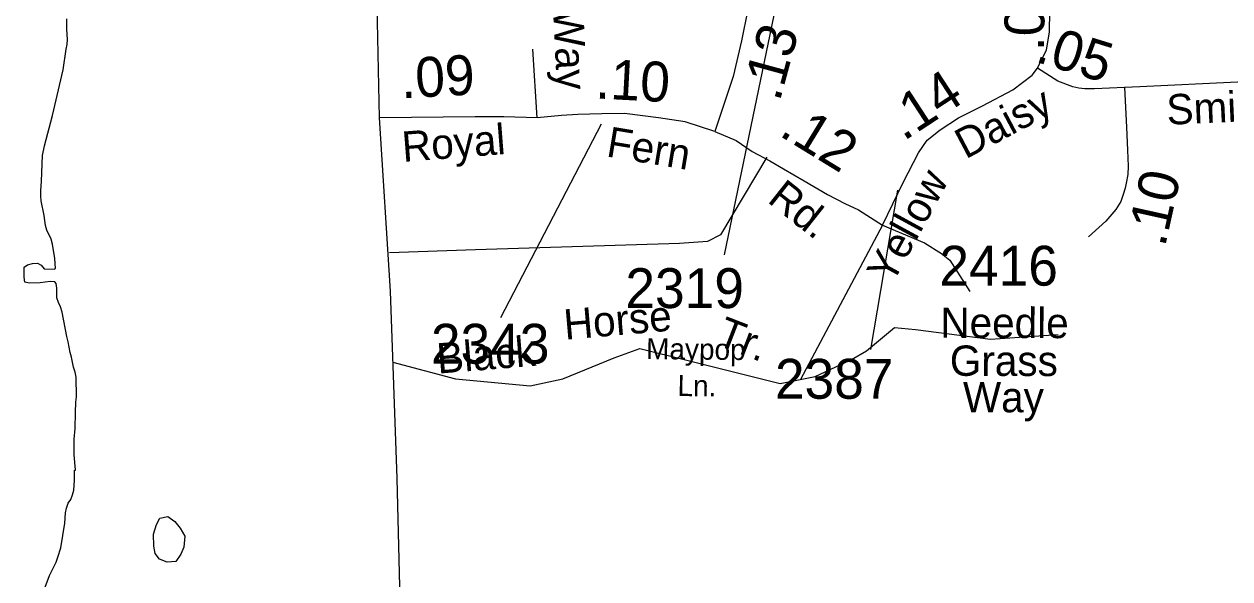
# Model space of a CAD drawing. Extents: x 2290055 to 2389491, y 66597 to 237875.
# Drawn here: x 2325602 to 2329384, y 120730 to 122469 of the extents above; entities that cross this region are included whole.
import ezdxf

# ---------------------------------------------------------------- set-up
doc = ezdxf.new("R2010")
doc.units = 0
for name, color, linetype in [('Exist Hydrographic Island Shore', 7, 'Continuous'), ('Exist Hydrographic Pond Under 1500 Sq Ft', 7, 'Continuous'), ('Exist Road Non-System Type 51', 7, 'Continuous'), ('Exist Road Non-System Type 51 Label', 7, 'Continuous'), ('Exist Road Secondary Mileage Hundredths English Label', 7, 'Continuous'), ('Exist Road Secondary Type 51 Attributed', 7, 'Continuous'), ('Exist Road Secondary Type 51 Label', 7, 'Continuous'), ('Exist Road Secondary Type 51 Number Label', 7, 'Continuous')]:
    doc.layers.add(name, color=color, linetype=linetype)

msp = doc.modelspace()

# ---------------------------------------------------------------- linework, layer by layer
at = {"layer": 'Exist Hydrographic Island Shore'}
msp.add_lwpolyline([(2325665.2, 120696.2), (2325681.5, 120740.3), (2325703.2, 120783), (2325708.5, 120798), (2325717, 120827.3), (2325730, 120904.5), (2325732.5, 120936.7), (2325735, 120952.2), (2325740, 120967.3), (2325749, 120979.4), (2325754.2, 120993.7), (2325758, 121008.6), (2325759.7, 121023.8), (2325760.5, 121040.1), (2325760.7, 121071), (2325763, 121070.6), (2325763.7, 121071.9), (2325759.7, 121119.2), (2325759.2, 121151), (2325759.5, 121167.7), (2325762.5, 121201.3), (2325763, 121251.3), (2325764.5, 121283.6), (2325766.5, 121300.9), (2325765.5, 121362.3), (2325762.7, 121377.8), (2325757.5, 121393.9), (2325751, 121425.5), (2325747, 121440.2), (2325740.2, 121473.6), (2325736.2, 121489.5), (2325722, 121566.5), (2325716.7, 121582.6), (2325710.5, 121596.2), (2325705.2, 121610.8), (2325704.5, 121641.3), (2325703.2, 121656.4), (2325698.7, 121661.7), (2325683.7, 121661.9), (2325668.5, 121660.7), (2325652.2, 121657.8), (2325619, 121656.8), (2325604, 121660.4), (2325602.2, 121675.6), (2325602.5, 121707.1), (2325613, 121715), (2325628.5, 121719), (2325644, 121720), (2325656, 121714), (2325665.5, 121701.7), (2325696.5, 121701.5), (2325700.2, 121703.5), (2325698.7, 121734.1), (2325691.7, 121779.9), (2325687.5, 121795.5), (2325673.5, 121822.9), (2325669, 121838), (2325665.2, 121869.5), (2325656, 121914.9), (2325654.5, 121930.1), (2325654.5, 121946.3), (2325657, 121977.1), (2325659.7, 122057.2), (2325666, 122087.7), (2325691.2, 122183), (2325724.7, 122326), (2325733.7, 122390.3), (2325737.7, 122405.5), (2325738.7, 122421.3), (2325736, 122453.8), (2325736, 122485.5)], dxfattribs=at)
at = {"layer": 'Exist Hydrographic Pond Under 1500 Sq Ft'}
msp.add_lwpolyline([(2326050.7, 120782.5), (2326027, 120792.4), (2326013, 120810.1), (2326009, 120832.9), (2326007.7, 120870.6), (2326017.5, 120900.4), (2326028, 120920.9), (2326053.2, 120925.4), (2326074.5, 120910.2), (2326092, 120889.6), (2326106, 120864.3), (2326103.5, 120829.9), (2326094.2, 120807.8), (2326078, 120785), (2326050.7, 120782.5)], dxfattribs=at)
at = {"layer": 'Exist Road Non-System Type 51'}
for points in [[(2327931.6, 122051.9), (2327786.7, 121808.3), (2327745.9, 121788.1), (2327657.5, 121781.4), (2327018.3, 121761.4), (2326748.4, 121752.4)], [(2328294.8, 121839.5), (2328037.4, 121355.5)], [(2328294.8, 121839.5), (2328426, 121783.1), (2328479.4, 121749.7), (2328506.1, 121729.7), (2328569.1, 121630.8)], [(2326759.2, 121409), (2326955.1, 121357.4), (2327189.6, 121335.4), (2327292.1, 121357.4), (2327453.3, 121423.4), (2327533.9, 121452.7), (2327680.5, 121416.1), (2327973.5, 121342.8), (2328083.5, 121364.8), (2328197, 121417.9), (2328244.6, 121445.4), (2328332.6, 121518.7), (2328398.5, 121511.4), (2328633, 121482.1), (2328845.4, 121496.7)]]:
    msp.add_lwpolyline(points, dxfattribs=at)
at = {"layer": 'Exist Road Secondary Type 51 Attributed'}
msp.add_line((2327211.3, 122175.8), (2327197.9, 122390.3), dxfattribs=at)
for points in [[(2326717.2, 122175.8), (2326707.1, 122627.5), (2326692.1, 123179.7)], [(2327862.1, 122788.2), (2327889.7, 122682.8), (2327884.7, 122612.5), (2327872.2, 122514.6), (2327852.1, 122416.7), (2327826.8, 122305), (2327769.3, 122132.2)], [(2328781.3, 122330.7), (2328809, 122389.1), (2328819, 122444.3), (2328819.6, 122510.2), (2328815.4, 122608.8), (2328809.3, 122710)], [(2330085.3, 122422.4), (2330035.4, 122426.9), (2330011, 122426.9), (2329988.9, 122426.5), (2329955.8, 122422.4), (2329927.2, 122417.8), (2329898.5, 122405.7), (2329827.7, 122373.7), (2329748.5, 122341.3), (2329674.2, 122319.2), (2329591.4, 122300.7), (2329536.6, 122291.9), (2329408.6, 122287), (2329102, 122272.9), (2329053.7, 122271)], [(2328294.8, 121839.5), (2328360, 121972.5), (2328407.7, 122065.4), (2328435.3, 122105.5), (2328475.4, 122138.1), (2328533.1, 122175.8), (2328608.3, 122213.4), (2328703.6, 122263.6), (2328763.8, 122308.8), (2328781.3, 122330.7)], [(2329053.7, 122271), (2328959.3, 122266.5), (2328929.6, 122266.1), (2328910.9, 122268), (2328891.5, 122272.9), (2328844.3, 122290.9), (2328781.3, 122330.7)], [(2329053.7, 122271), (2329060.5, 122145.7), (2329063.6, 122074.2), (2329065.1, 122023.7), (2329064.2, 121998.1), (2329059.3, 121970.3), (2329055.9, 121955.2), (2329049.8, 121934.8), (2329041.9, 121913.2), (2329027, 121888.2), (2328995.7, 121851.1), (2328940.6, 121802.1)], [(2327211.3, 122175.8), (2327107.2, 122178.3), (2327016.9, 122178.3), (2326717.2, 122175.8)], [(2326929.9, 116468.6), (2326914.2, 116526.2), (2326903.7, 116604.7), (2326893.2, 116772.3), (2326885.4, 117136.2), (2326877, 117384.2), (2326871.6, 117896.1), (2326831.4, 119069.9), (2326815.4, 119571.1), (2326794, 120155.3), (2326772.5, 121045), (2326751.1, 121631.9), (2326717.2, 122175.8)], [(2327769.3, 122132.2), (2327675.4, 122162.6), (2327592.5, 122175.8), (2327485.2, 122189.4), (2327414.4, 122188.3), (2327339.2, 122185.8), (2327287.8, 122183.3), (2327211.3, 122175.8)], [(2327769.3, 122132.2), (2327835.6, 122104.5), (2327886, 122070.4), (2327941.2, 122040.3), (2327983.8, 122015.2), (2328049, 121977.5), (2328121.7, 121934.9), (2328176.9, 121907.3), (2328219.6, 121887.2), (2328294.8, 121839.5)]]:
    msp.add_lwpolyline(points, dxfattribs=at)
at = {"layer": 'Exist Road Secondary Type 51 Number Label'}
for p, q in [((2328020.4, 122817.7), (2327798.1, 121745.6)), ((2327412.7, 122155.7), (2327096.5, 121548)), ((2328341.5, 121948.2), (2328257.5, 121449.2))]:
    msp.add_line(p, q, dxfattribs=at)

# ---------------------------------------------------------------- texts
at = {"layer": 'Exist Road Non-System Type 51 Label'}
for s, rotation, p in [('Horse', 4.9412, (2327299, 121479.7)), ('Tr.', 338.8588, (2327769.3, 121465.4)), ('Black', 4.6452, (2326900.3, 121373.4))]:
    msp.add_text(s, height=95, rotation=rotation, dxfattribs=at).set_placement(p)
at = {"layer": 'Exist Road Secondary Mileage Hundredths English Label'}
for s, rotation, p in [('.07', 89.4944, (2328801.5, 122384.2)), ('.13', 74.7563, (2327971.8, 122223.4)), ('.05', 342.8308, (2328770.2, 122352.6)), ('.09', 3.157, (2326786.3, 122236.5)), ('.10', 356.9854, (2327392.7, 122236.5)), ('.14', 33.1272, (2328361, 122100.9)), ('.12', 328.5436, (2327966.9, 122121.7)), ('.10', 77.5084, (2329180.5, 121767.7))]:
    msp.add_text(s, height=125, rotation=rotation, dxfattribs=at).set_placement(p)
at = {"layer": 'Exist Road Secondary Type 51 Label'}
for s, height, rotation, p in [('Willow Way', 95, 272.8985, (2327240.8, 122916.9)), ('Daisy', 95, 27.8067, (2328555.2, 122044.8)), ('Smilax', 95, 2.6221, (2329187.7, 122153.5)), ('Royal', 95, 4.4706, (2326791, 122037.1)), ('Fern', 95, 350.5304, (2327425.5, 122054.9)), ('Yellow', 95, 61.4208, (2328324.8, 121650.6)), ('Rd.', 95, 321.6107, (2327930.3, 121913.4)), ('Needle', 95, 359.8228, (2328476.1, 121485.9)), ('Maypop', 65.62, 359.4391, (2327553, 121419.1)), ('Grass', 95, 359.8228, (2328505.8, 121366.9)), ('Ln.', 65.62, 359.4391, (2327651.5, 121303.3)), ('Way', 95, 359.8228, (2328546.7, 121252.8))]:
    msp.add_text(s, height=height, rotation=rotation, dxfattribs=at).set_placement(p)
at = {"layer": 'Exist Road Secondary Type 51 Number Label'}
for s, p in [('2416', (2328473.1, 121649.4)), ('2319', (2327488.2, 121579.1)), ('2343', (2326878.2, 121404.7)), ('2387', (2327957.3, 121294.8))]:
    msp.add_text(s, height=125, dxfattribs=at).set_placement(p)

doc.saveas('drawing.dxf')
